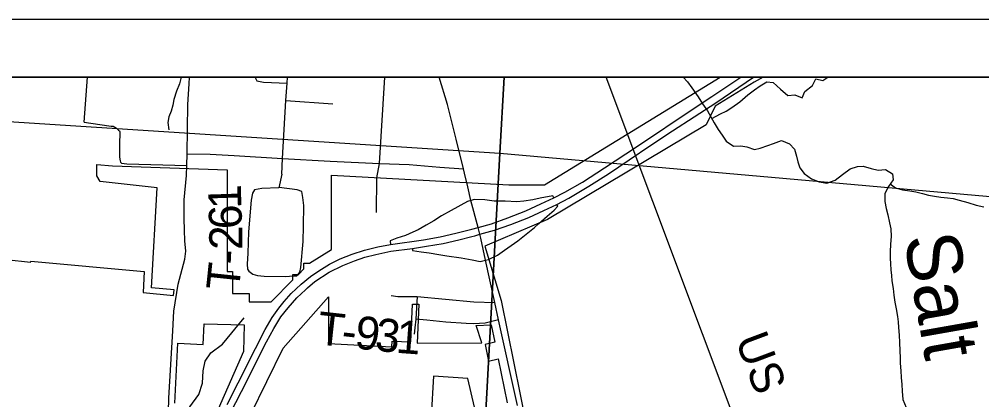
# Model space of a CAD drawing. Extents: x 0 to 34, y 0 to 22.
# Drawn here: x 27.717 to 29.378, y 20.344 to 21 of the extents above; entities that cross this region are included whole.
import ezdxf

# ---------------------------------------------------------------- set-up
doc = ezdxf.new("R2010")
doc.units = 0
for name, color, linetype in [('GM_X_City_Street', 7, 'Continuous'), ('GM_X_Corporation', 7, 'Continuous'), ('GM_X_Interchange_Ramps', 7, 'Continuous'), ('GM_X_Major_River', 7, 'Continuous'), ('GM_X_Major_River_Text', 7, 'Continuous'), ('GM_X_Minor_River', 7, 'Continuous'), ('GM_X_Rail_Line', 7, 'Continuous'), ('GM_X_Rail_Line_Text', 7, 'Continuous'), ('GM_X_State_Route', 7, 'Continuous'), ('GM_X_Township_Road', 7, 'Continuous'), ('GM_X_Township_Road_Text', 7, 'Continuous'), ('SH_Data', 7, 'Continuous')]:
    doc.layers.add(name, color=color, linetype=linetype)

msp = doc.modelspace()

# ---------------------------------------------------------------- linework, layer by layer
at = {"layer": 'GM_X_City_Street'}
for p, q in [((27.829, 20.8226), (27.8351, 20.9)), ((28.1772, 20.8601), (28.2579, 20.8545))]:
    msp.add_line(p, q, dxfattribs=at)
for points in [[(28.006, 20.7479), (28.0068, 20.7681), (28.0082, 20.8534), (28.0101, 20.8887), (28.0108, 20.9)], [(28.1243, 20.9), (28.1243, 20.8997), (28.1271, 20.894), (28.1384, 20.8918), (28.1792, 20.8898)], [(28.1702, 20.733), (28.1713, 20.76), (28.1772, 20.8601), (28.1792, 20.8898), (28.1797, 20.9)], [(28.3343, 20.7267), (28.3384, 20.7516), (28.3477, 20.9)], [(27.829, 20.8226), (27.8407, 20.8207), (27.8756, 20.816), (27.8789, 20.8155), (27.8821, 20.814), (27.8851, 20.8121), (27.8883, 20.8091), (27.8901, 20.8075), (27.8908, 20.8059), (27.8899, 20.7835), (27.8901, 20.7623), (27.8909, 20.7563), (27.892, 20.7536), (27.8935, 20.752), (27.9029, 20.7507), (28.006, 20.7479)], [(28.0068, 20.7681), (28.0467, 20.7675), (28.0876, 20.7652), (28.1713, 20.76), (28.2536, 20.7557), (28.3384, 20.7516), (28.3901, 20.7498), (28.4428, 20.7453), (28.4837, 20.7423)], [(28.1702, 20.733), (28.165, 20.7095), (28.1356, 20.7083), (28.1228, 20.7061), (28.1194, 20.7004), (28.1175, 20.6884), (28.1129, 20.6335), (28.1114, 20.5971), (28.1105, 20.5777), (28.111, 20.5693), (28.1133, 20.5661), (28.1203, 20.561), (28.1282, 20.5582), (28.1398, 20.5573), (28.1756, 20.5568), (28.1909, 20.5576), (28.1956, 20.5579), (28.1984, 20.5601), (28.2012, 20.5643), (28.203, 20.5722), (28.2067, 20.6172), (28.2077, 20.6433), (28.2081, 20.6791), (28.2063, 20.693), (28.2044, 20.703), (28.1965, 20.706), (28.1657, 20.7102)], [(27.974, 20.3147), (27.9924, 20.3196), (28.0113, 20.3318), (28.0268, 20.3535), (28.0332, 20.3726), (28.0345, 20.3943), (28.0378, 20.4106), (28.0477, 20.4249), (28.068, 20.4401), (28.1054, 20.4857)]]:
    msp.add_lwpolyline(points, dxfattribs=at)
at = {"layer": 'GM_X_Corporation'}
for points in [[(27.713, 19.8126), (27.7479, 19.8098), (27.921, 19.7976), (28.0078, 19.7898), (28.15, 19.7813), (28.3845, 19.7702), (28.4743, 19.7657), (28.6835, 19.7478), (28.7311, 19.743), (28.8977, 19.7297), (28.9889, 19.7198), (29.3495, 19.6807), (29.4353, 19.675), (29.5232, 19.6666), (30.3167, 19.5906), (30.3167, 20.9), (26.3743, 20.9)], [(27.484, 20.6087), (27.7367, 20.5812), (27.7368, 20.5832), (27.9328, 20.5653), (27.9308, 20.529), (27.9832, 20.5242), (27.9841, 20.5336), (27.9454, 20.5372), (27.9551, 20.7096), (27.8565, 20.7204), (27.8511, 20.7302), (27.8508, 20.7499), (27.8779, 20.7477), (28.0757, 20.7406), (28.0757, 20.5652), (28.0852, 20.5652), (28.0852, 20.5273), (28.1136, 20.5273), (28.1136, 20.5131), (28.1515, 20.5131), (28.1893, 20.5509), (28.1893, 20.5604), (28.1988, 20.5604), (28.2083, 20.5699), (28.2083, 20.5794), (28.2178, 20.5794), (28.2556, 20.603), (28.2556, 20.7314), (28.5616, 20.7149), (28.6232, 20.7149), (28.9263, 20.9), (26.5396, 20.9)], [(29.467, 20.9), (29.0005, 20.9), (28.9851, 20.8915), (28.9177, 20.8504), (28.9024, 20.8183), (28.6286, 20.6551), (28.5205, 20.6089), (28.5483, 20.5152), (28.5921, 20.2996)], [(28.1162, 20.3183), (28.1722, 20.4332), (28.2508, 20.5218), (28.2508, 20.441), (28.3599, 20.4357), (28.3605, 20.4454), (28.3929, 20.4443), (28.3957, 20.5088), (28.4067, 20.5088), (28.4038, 20.4416), (28.5154, 20.4423), (28.5052, 20.4724), (28.5316, 20.4734), (28.5376, 20.4436), (28.5209, 20.4394), (28.5267, 20.4106), (28.5435, 20.4146), (28.5589, 20.339)], [(27.9853, 20.3383), (27.9907, 20.4417), (28.0342, 20.4395), (28.0361, 20.4754), (28.1052, 20.4732), (28.1042, 20.4275), (28.0603, 20.3279)], [(28.5157, 20.2749), (28.4908, 20.3808), (28.4317, 20.3852), (28.424, 20.2468)]]:
    msp.add_lwpolyline(points, dxfattribs=at)
for points in [[(28.5537, 20.9), (27.5066, 20.9), (27.5018, 20.8365), (28.5465, 20.7695)], [(29.5485, 20.9), (28.5537, 20.9), (28.5465, 20.7695), (29.5293, 20.6826)], [(27.5018, 20.8365), (28.5465, 20.7695), (28.4917, 19.7627), (28.3876, 19.7694), (27.4311, 19.8373)], [(28.5465, 20.7695), (29.5293, 20.6826), (29.4415, 19.6802), (29.3585, 19.6871), (28.4917, 19.7627)]]:
    msp.add_lwpolyline(points, close=True, dxfattribs=at)
at = {"layer": 'GM_X_Interchange_Ramps'}
msp.add_line((28.5218, 20.5849), (28.5266, 20.5859), dxfattribs=at)
for points in [[(28.6394, 20.6923), (28.6377, 20.6959), (28.6159, 20.6915), (28.6034, 20.6889), (28.5874, 20.6866), (28.5756, 20.6852), (28.5553, 20.6863), (28.5367, 20.6868), (28.5203, 20.6887), (28.5025, 20.6892), (28.4964, 20.6877)], [(28.4964, 20.6877), (28.4904, 20.6858), (28.4624, 20.6705), (28.4455, 20.6611), (28.4324, 20.6528), (28.4193, 20.6452), (28.4052, 20.6374), (28.3961, 20.633), (28.3834, 20.6275), (28.3684, 20.6229), (28.3571, 20.6181), (28.3575, 20.6117)], [(28.6138, 20.648), (28.6278, 20.6605), (28.6402, 20.6709), (28.6465, 20.6779), (28.6447, 20.681)], [(28.5266, 20.5859), (28.5424, 20.5937), (28.5545, 20.6018), (28.5773, 20.6179), (28.606, 20.641), (28.6138, 20.648)], [(28.3955, 20.6052), (28.3956, 20.6013), (28.4108, 20.599), (28.4241, 20.5974), (28.441, 20.5948), (28.455, 20.5923), (28.4794, 20.5886), (28.4987, 20.5852), (28.5126, 20.5827), (28.5218, 20.5849)]]:
    msp.add_lwpolyline(points, dxfattribs=at)
at = {"layer": 'GM_X_Major_River'}
for points in [[(28.8626, 20.9), (28.8699, 20.8923), (28.8778, 20.882), (28.8883, 20.8663), (28.8962, 20.8541), (28.9044, 20.8423), (28.9104, 20.8316), (28.9163, 20.8213), (28.9231, 20.8103), (28.9298, 20.8), (28.9369, 20.7901), (28.9497, 20.7812), (28.9622, 20.7819), (28.9725, 20.7803), (28.9857, 20.7756), (28.9956, 20.7778), (29.0089, 20.7823), (29.0184, 20.786), (29.0321, 20.7908), (29.046, 20.7854), (29.0547, 20.7759), (29.0584, 20.7641), (29.0602, 20.7542), (29.0639, 20.7439), (29.0714, 20.7344), (29.0838, 20.7252), (29.0974, 20.7197), (29.1106, 20.7174), (29.1251, 20.7229), (29.1377, 20.7327), (29.1506, 20.7425), (29.1632, 20.7462), (29.1734, 20.7468), (29.187, 20.7426), (29.1991, 20.7402), (29.212, 20.7412), (29.2237, 20.7335), (29.2251, 20.7233), (29.2167, 20.7116), (29.2105, 20.6995), (29.2108, 20.6858), (29.213, 20.6741), (29.2159, 20.6627), (29.2188, 20.649), (29.221, 20.6391), (29.2213, 20.6254), (29.2204, 20.6125), (29.2196, 20.5993), (29.2195, 20.5883), (29.2201, 20.5784), (29.2212, 20.5681), (29.2222, 20.5586), (29.2229, 20.5492), (29.2247, 20.5359), (29.2261, 20.5248), (29.2279, 20.5127), (29.2301, 20.5009), (29.2326, 20.488), (29.2337, 20.4785)], [(29.2337, 20.4785), (29.234, 20.4686), (29.2354, 20.4557), (29.2357, 20.4432), (29.2363, 20.4284), (29.237, 20.4166), (29.2373, 20.4071), (29.2383, 20.3942), (29.239, 20.3825), (29.24, 20.3707), (29.2407, 20.3593), (29.2417, 20.3445), (29.2476, 20.3312)]]:
    msp.add_lwpolyline(points, dxfattribs=at)
at = {"layer": 'GM_X_Minor_River'}
for points in [[(27.9963, 20.9), (27.9933, 20.8888), (27.9886, 20.8759), (27.9836, 20.8615), (27.982, 20.8517), (27.9793, 20.8418), (27.9751, 20.832), (27.9735, 20.8222), (27.9753, 20.8092)], [(28.9119, 20.8289), (28.9271, 20.8373), (28.9366, 20.8418), (28.9468, 20.8482), (28.9601, 20.858), (28.9742, 20.8697), (28.9859, 20.8784), (28.9954, 20.8852), (29.0068, 20.8924), (29.0181, 20.8908), (29.0306, 20.8794), (29.0434, 20.8684), (29.0555, 20.8695), (29.068, 20.8645), (29.0726, 20.8758), (29.0859, 20.886), (29.0916, 20.8974), (29.1037, 20.8947), (29.112, 20.9)], [(29.22, 20.7162), (29.2287, 20.7096), (29.2408, 20.7058), (29.2536, 20.7046), (29.2642, 20.7027), (29.2756, 20.7), (29.2862, 20.6969), (29.296, 20.695), (29.3074, 20.6934), (29.3187, 20.6922), (29.3285, 20.6911), (29.3391, 20.6884), (29.3539, 20.6842), (29.3682, 20.6796), (29.3815, 20.6765)]]:
    msp.add_lwpolyline(points, dxfattribs=at)
at = {"layer": 'GM_X_Rail_Line'}
msp.add_lwpolyline([(29.1913, 19.6716), (29.1345, 19.823), (28.9817, 20.2298), (28.8105, 20.6857), (28.73, 20.9)], dxfattribs=at)
at = {"layer": 'GM_X_State_Route'}
for p, q in [((28.4909, 20.7111), (28.4855, 20.7345)), ((28.5767, 20.3343), (28.5439, 20.4822))]:
    msp.add_line(p, q, dxfattribs=at)
for points in [[(28.076, 20.3361), (28.0946, 20.3736), (28.1246, 20.4327), (28.1415, 20.4656), (28.1535, 20.4863), (28.1652, 20.5022), (28.1742, 20.5138), (28.1862, 20.5276), (28.2032, 20.5437), (28.2196, 20.5567), (28.2339, 20.5667), (28.2524, 20.5777), (28.2708, 20.587), (28.2914, 20.5953), (28.3129, 20.6021), (28.3358, 20.6077), (28.3575, 20.6117), (28.4145, 20.6201), (28.4431, 20.625), (28.4703, 20.6311), (28.4977, 20.6383), (28.5087, 20.6413), (28.5318, 20.6477), (28.5599, 20.6577), (28.5912, 20.6699), (28.617, 20.6818), (28.6394, 20.6923), (28.6585, 20.7022), (28.6891, 20.7194), (28.7267, 20.7442), (28.7636, 20.7679), (28.8008, 20.7929), (28.8625, 20.8344), (28.9121, 20.8667), (28.9621, 20.9)], [(28.4708, 20.7936), (28.4559, 20.853), (28.4415, 20.9)], [(28.6798, 20.7004), (28.6996, 20.7121), (28.7335, 20.7336), (28.7695, 20.758), (28.8069, 20.783), (28.8444, 20.808), (28.9189, 20.8562), (28.9837, 20.9)], [(28.4855, 20.7345), (28.4837, 20.7423), (28.4708, 20.7936)], [(28.5134, 20.6228), (28.5119, 20.6295), (28.5087, 20.6413), (28.4964, 20.6877), (28.4909, 20.7111)], [(28.6447, 20.681), (28.6652, 20.6917), (28.6798, 20.7004)], [(28.498, 20.6257), (28.503, 20.627), (28.5119, 20.6295), (28.5371, 20.6364), (28.5652, 20.6465), (28.5965, 20.6586), (28.6223, 20.6705), (28.6447, 20.681)], [(28.3955, 20.6052), (28.4198, 20.6088), (28.4484, 20.6137), (28.4756, 20.6198), (28.498, 20.6257)], [(28.5439, 20.4822), (28.5375, 20.5117), (28.5218, 20.5849), (28.5134, 20.6228)], [(28.2146, 20.5369), (28.2273, 20.5481), (28.252, 20.564), (28.2752, 20.5759), (28.2954, 20.5836), (28.3135, 20.59), (28.3321, 20.5946), (28.3583, 20.6002), (28.3955, 20.6052)], [(27.971, 20.1844), (27.9819, 20.1926), (28.0081, 20.2168), (28.0285, 20.2387), (28.0443, 20.2592), (28.0576, 20.2786), (28.0706, 20.3002), (28.1007, 20.3587), (28.1434, 20.444), (28.1563, 20.4673), (28.1683, 20.4869), (28.1808, 20.5027), (28.1961, 20.52), (28.2109, 20.5336), (28.2146, 20.5369)]]:
    msp.add_lwpolyline(points, dxfattribs=at)
at = {"layer": 'GM_X_Township_Road'}
msp.add_line((28.3336, 20.6672), (28.3343, 20.7267), dxfattribs=at)
for points in [[(27.9753, 20.3469), (27.9819, 20.4629), (27.9838, 20.4967), (27.9914, 20.5435), (28.0026, 20.5863), (28.0044, 20.6004), (28.003, 20.618), (28.0021, 20.6368), (28.0016, 20.6567), (28.0016, 20.6725), (28.0018, 20.6889), (28.0054, 20.731), (28.006, 20.7479)], [(28.3589, 20.5237), (28.3704, 20.5224), (28.4039, 20.5224), (28.5012, 20.5131), (28.5375, 20.5117)], [(28.4039, 20.5224), (28.4016, 20.4832), (28.3997, 20.4681), (28.3984, 20.4575)], [(28.5439, 20.4822), (28.5208, 20.476), (28.5012, 20.4752), (28.488, 20.4757), (28.453, 20.4781), (28.4206, 20.4816), (28.4016, 20.4832)], [(27.9543, 20.2471), (27.9559, 20.2499), (27.9651, 20.2666), (27.9692, 20.2773), (27.9717, 20.2908), (27.974, 20.3147), (27.975, 20.3418), (27.9753, 20.3469)]]:
    msp.add_lwpolyline(points, dxfattribs=at)
at = {"layer": 'SH_Data'}
for points in [[(23.4167, 21), (30.4167, 21), (30.4167, 14), (23.4167, 14)], [(23.5167, 20.9), (30.3167, 20.9), (30.3167, 14.1), (23.5167, 14.1)]]:
    msp.add_lwpolyline(points, close=True, dxfattribs=at)

# ---------------------------------------------------------------- texts
at = {"layer": 'GM_X_Major_River_Text'}
msp.add_text('Salt', height=0.09471, rotation=279.9997, dxfattribs=at).set_placement((29.2431, 20.6242))
at = {"layer": 'GM_X_Rail_Line_Text'}
msp.add_text('US', height=0.05663, rotation=290.6025, dxfattribs=at).set_placement((28.952, 20.4479))
at = {"layer": 'GM_X_Township_Road_Text'}
for s, rotation, p in [('1', 91.831, (28.1006, 20.6739)), ('6', 91.8338, (28.1017, 20.6392)), ('2', 90.0162, (28.1017, 20.6025)), ('-', 87.221, (28.1005, 20.5764)), ('T', 84.0275, (28.0959, 20.5307)), ('T', 353.6868, (28.2293, 20.4402)), ('9', 353.6868, (28.2944, 20.433)), ('3', 354.0744, (28.3293, 20.4292)), ('1', 355.7358, (28.3657, 20.4254)), ('-', 353.6868, (28.2714, 20.4356))]:
    msp.add_text(s, height=0.0568, rotation=rotation, dxfattribs=at).set_placement(p)

doc.saveas('drawing.dxf')
